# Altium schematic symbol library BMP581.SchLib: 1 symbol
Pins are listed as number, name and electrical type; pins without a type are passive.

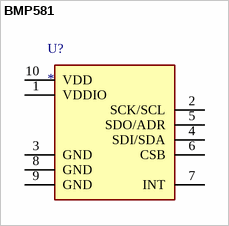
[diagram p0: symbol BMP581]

## BMP581
designator U?
Very small, low-power and low noise 24-bit absolute barometric pressure sensor. This digital, high-performance sensor is ideally suited for a wide range of altitude tracking applications and offers outstanding design flexibility; MF: Bosch; MP: BMP581
footprint BMP581
pins: 1 VDDIO, 2 SCK/SCL, 3 GND, 4 SDI/SDA, 5 SDO/ADR, 6 CSB, 7 INT, 8 GND, 9 GND, 10 VDD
